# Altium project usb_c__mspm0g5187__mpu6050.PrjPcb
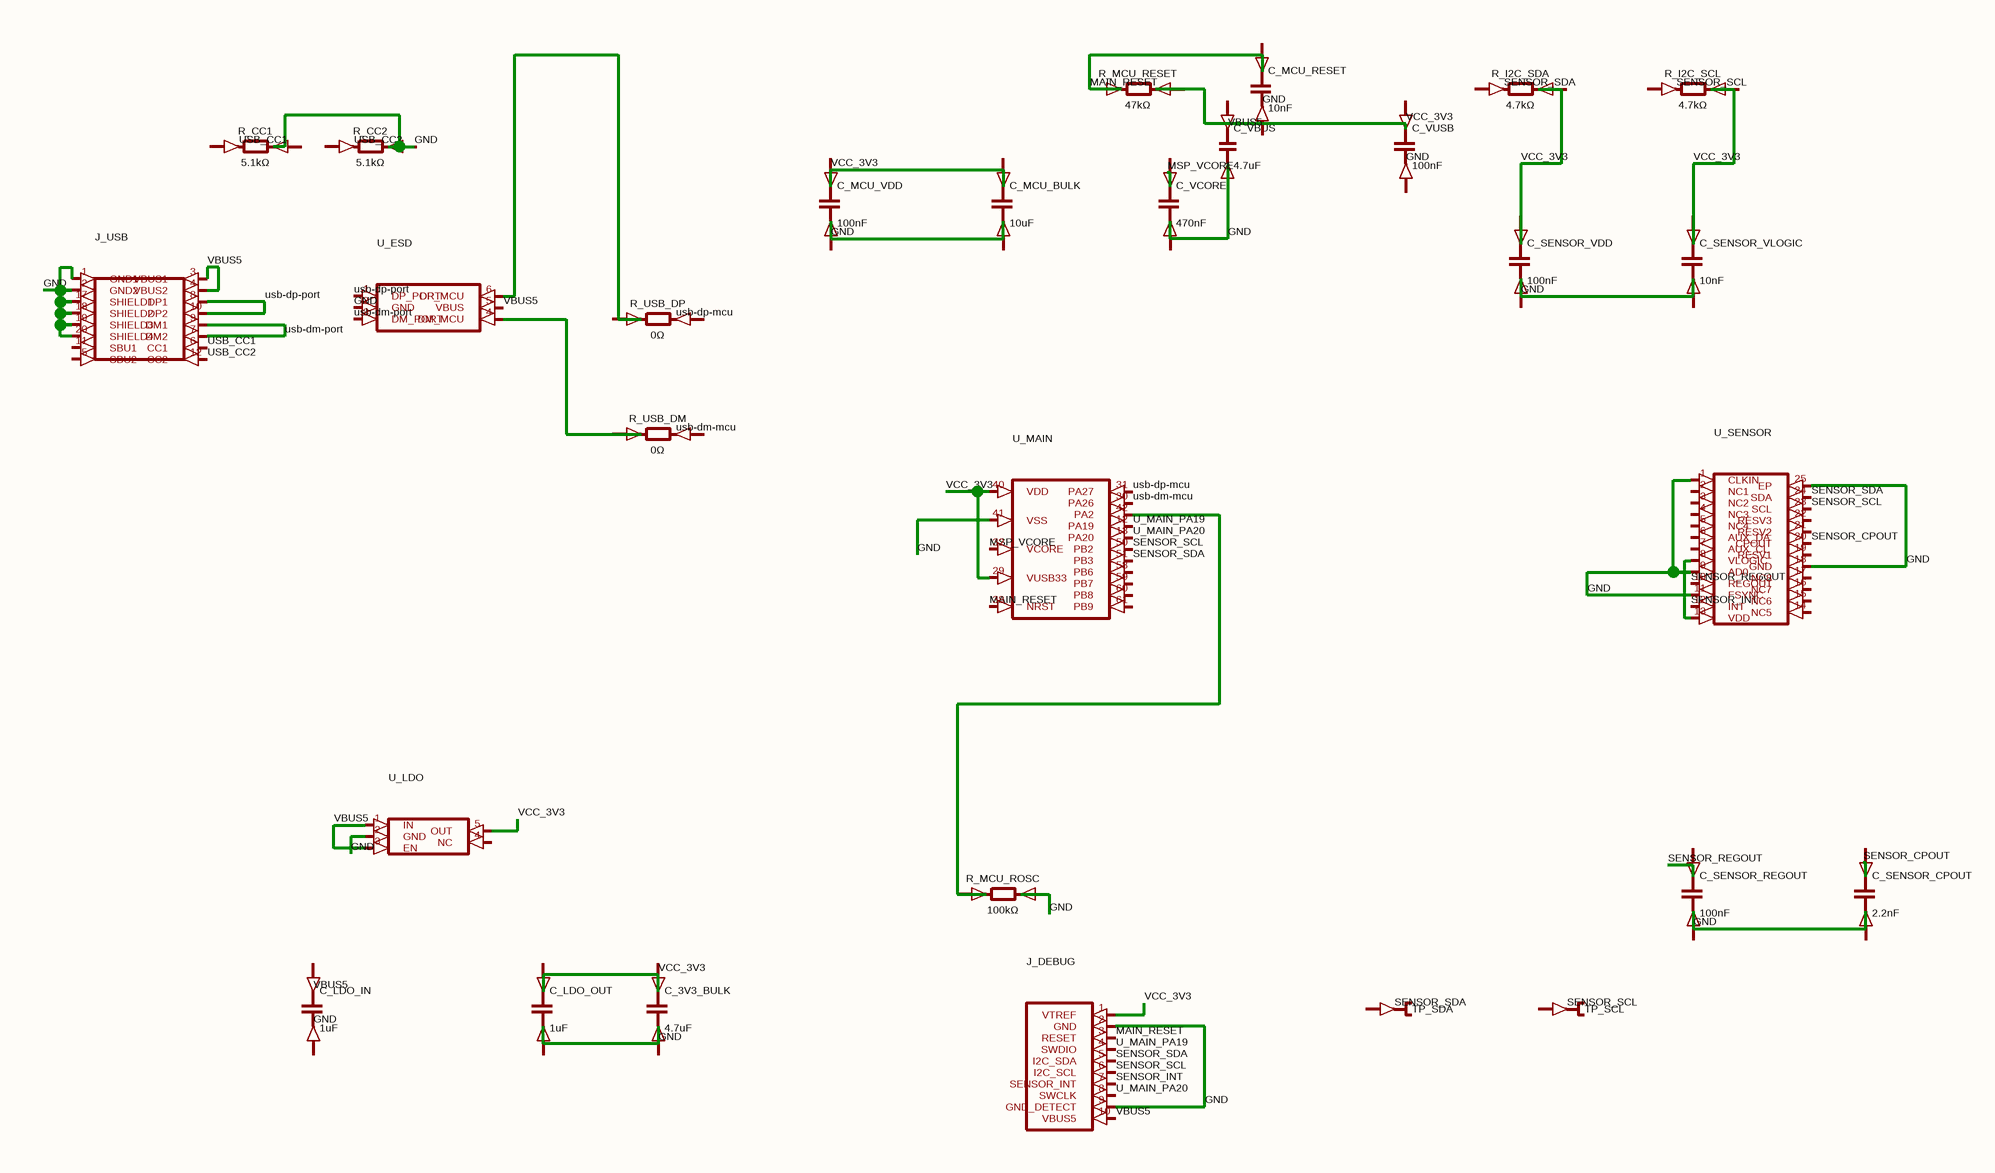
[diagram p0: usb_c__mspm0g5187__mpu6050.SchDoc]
1 sheet, 29 parts. Net scope: global (net labels, ports and power ports of the same name join across sheets).
Board file: usb_c__mspm0g5187__mpu6050.PcbDoc

## Sheet usb_c__mspm0g5187__mpu6050.SchDoc
size 215 x 144 mm

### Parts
C_3V3_BULK  4.7uF
C_LDO_IN  1uF
C_LDO_OUT  1uF
C_MCU_BULK  10uF
C_MCU_RESET  10nF
C_MCU_VDD  100nF
C_SENSOR_CPOUT  2.2nF
C_SENSOR_REGOUT  100nF
C_SENSOR_VDD  100nF
C_SENSOR_VLOGIC  10nF
C_VBUS  4.7uF
C_VCORE  470nF
C_VUSB  100nF
J_DEBUG  (no value)
J_USB  (no value)
R_CC1  5.1kΩ
R_CC2  5.1kΩ
R_I2C_SCL  4.7kΩ
R_I2C_SDA  4.7kΩ
R_MCU_RESET  47kΩ
R_MCU_ROSC  100kΩ
R_USB_DM  0Ω
R_USB_DP  0Ω
TP_SCL  (no value)
TP_SDA  (no value)
U_ESD  (no value)
U_LDO  (no value)
U_MAIN  (no value)
U_SENSOR  (no value)

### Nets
GND: C_SENSOR_VDD.1(anode) C_SENSOR_VLOGIC.1(anode) C_VBUS.2(cathode) J_DEBUG.1(VTREF) J_DEBUG.2(GND) J_DEBUG.9(GND_DETECT) J_DEBUG.10(VBUS5) J_USB.1(GND1) J_USB.2(GND2) J_USB.3(VBUS1) J_USB.4(VBUS2) J_USB.17(SHIELD1) J_USB.18(SHIELD2) J_USB.19(SHIELD3) J_USB.20(SHIELD4) R_MCU_RESET.2(cathode) R_MCU_ROSC.2(cathode) U_ESD.2(GND) U_ESD.5(VBUS) U_LDO.1(IN) U_LDO.2(GND) U_LDO.3(EN) U_LDO.5(OUT) U_MAIN.29(VUSB33) U_MAIN.40(VDD) U_MAIN.41(VSS) U_SENSOR.1(CLKIN) U_SENSOR.8(VLOGIC) U_SENSOR.9(AD0) U_SENSOR.11(FSYNC) U_SENSOR.13(VDD) U_SENSOR.18(GND) U_SENSOR.25(EP)  [also labelled VBUS5, VCC_3V3]
MAIN_RESET: J_DEBUG.3(RESET) R_MCU_RESET.1(anode) U_MAIN.38(NRST)
MSP_VCORE: U_MAIN.32(VCORE)
SENSOR_CPOUT: U_SENSOR.20(CPOUT)
SENSOR_INT: J_DEBUG.7(SENSOR_INT) U_SENSOR.12(INT)
SENSOR_REGOUT: U_SENSOR.10(REGOUT)
SENSOR_SCL: J_DEBUG.6(I2C_SCL) U_MAIN.50(PB2) U_SENSOR.23(SCL)
SENSOR_SDA: J_DEBUG.5(I2C_SDA) U_MAIN.51(PB3) U_SENSOR.24(SDA)
U_MAIN_PA19: J_DEBUG.4(SWDIO) U_MAIN.12(PA19)
U_MAIN_PA20: J_DEBUG.8(SWCLK) U_MAIN.13(PA20)
usb-dm-mcu: U_MAIN.30(PA26)
usb-dm-port: J_USB.7(DM2) J_USB.9(DM1) U_ESD.3(DM_PORT)
usb-dp-mcu: U_MAIN.31(PA27)
usb-dp-port: J_USB.8(DP1) J_USB.10(DP2) U_ESD.1(DP_PORT)
USB_CC1: J_USB.6(CC1)
USB_CC2: J_USB.12(CC2)
NetR_MCU_ROSC_1: R_MCU_ROSC.1(anode) U_MAIN.42(PA2)
NetR_USB_DM_1: R_USB_DM.1(anode) U_ESD.4(DM_MCU)

Not connected (* = marked no-connect by the designer): C_3V3_BULK 1(anode) 2(cathode); C_LDO_IN 1(anode) 2(cathode); C_LDO_OUT 1(anode) 2(cathode); C_MCU_BULK 1(anode) 2(cathode); C_MCU_RESET 1(anode) 2(cathode); C_MCU_VDD 1(anode) 2(cathode); C_SENSOR_CPOUT 1(anode) 2(cathode); C_SENSOR_REGOUT 1(anode) 2(cathode); C_SENSOR_VDD 2(cathode); C_SENSOR_VLOGIC 2(cathode); C_VBUS 1(anode); C_VCORE 1(anode) 2(cathode); C_VUSB 1(anode) 2(cathode); J_USB 5(SBU2) 11(SBU1); R_CC1 1(anode) 2(cathode); R_CC2 1(anode) 2(cathode); R_I2C_SCL 1(anode) 2(cathode); R_I2C_SDA 1(anode) 2(cathode); R_USB_DM 2(cathode); R_USB_DP 1(anode) 2(cathode); TP_SCL 1(pin1); TP_SDA 1(pin1); U_ESD 6(DP_MCU); U_LDO 4(NC); U_MAIN 58(PB6) 59(PB7) 60(PB8) 61(PB9); U_SENSOR 2(NC1) 3(NC2) 4(NC3) 5(NC4) 6(AUX_DA) 7(AUX_CL) 14(NC5) 15(NC6) 16(NC7) 17(NC8) 19(RESV1) 21(RESV2) 22(RESV3)

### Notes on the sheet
- Labels drawn without touching a wire or pin: GND, SENSOR_SCL, SENSOR_SDA, usb-dm-mcu, usb-dp-mcu, USB_CC1, USB_CC2, VBUS5

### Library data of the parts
C_3V3_BULK C_LDO_IN C_LDO_OUT C_MCU_BULK C_MCU_RESET C_MCU_VDD C_SENSOR_CPOUT C_SENSOR_REGOUT C_SENSOR_VDD C_SENSOR_VLOGIC C_VBUS C_VCORE C_VUSB = capacitor_down
J_DEBUG = J_DEBUG
J_USB = J_USB
R_CC1 R_CC2 R_I2C_SCL R_I2C_SDA R_MCU_RESET R_MCU_ROSC R_USB_DM R_USB_DP = boxresistor_right
TP_SCL TP_SDA = testpoint_right
U_ESD = U_ESD
U_LDO = U_LDO
U_MAIN = U_MAIN
U_SENSOR = U_SENSOR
